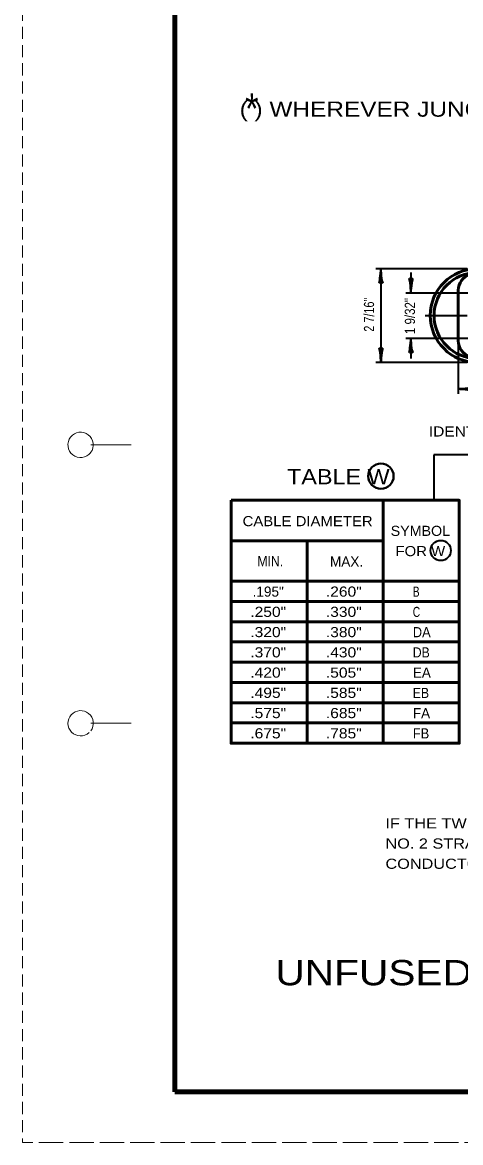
# Model space of a CAD drawing. Extents: x -1 to 679, y 0 to 440.
# Drawn here: x -1.3 to 85.1, y -0.1 to 221.2 of the extents above; entities that cross this region are included whole.
import ezdxf
from ezdxf.enums import TextEntityAlignment as Align

# ---------------------------------------------------------------- set-up
doc = ezdxf.new("R2010")
doc.units = 0
doc.header["$LTSCALE"] = 0.8
doc.linetypes.add('LONG_DASHED', pattern=[7.5, 6, -1.5])
doc.linetypes.add('MEDIUM_DASHED', pattern=[4.5, 3, -1.5])
doc.layers.add('1', color=7, linetype='Continuous', lineweight=53)
doc.layers.add('61', color=7, linetype='Continuous', lineweight=35)

msp = doc.modelspace()

# ---------------------------------------------------------------- linework, layer by layer
at = {"layer": '1', "linetype": 'MEDIUM_DASHED', "lineweight": 13}
msp.add_line((-1.285, 439.9088), (-1.345, -0.1312), dxfattribs=at)
at = {"layer": '1', "lineweight": 35}
for p, q in [((86.3878, 172.5118), (68.3878, 172.5118)), ((69.3878, 172.5118), (69.3878, 154.0118)), ((75.3062, 171.7618), (75.3062, 167.7618)), ((74.3062, 167.7618), (87.3878, 167.7618)), ((78.1378, 163.2618), (86.3878, 163.2618)), ((74.3062, 158.7618), (87.3878, 158.7618)), ((75.3062, 158.7618), (75.3062, 154.7618)), ((84.6378, 157.2618), (84.6378, 147.7618)), ((86.3878, 154.0118), (68.3878, 154.0118)), ((84.6378, 148.7618), (92.1378, 148.7618)), ((122.1378, 135.7618), (79.8449, 135.7618)), ((79.8449, 135.7618), (79.8449, 126.7763))]:
    msp.add_line(p, q, dxfattribs=at)
at = {"layer": '1'}
for p, q in [((84.6378, 167.7618), (84.6378, 163.2618)), ((84.6378, 163.2618), (84.6378, 158.7618)), ((69.8449, 78.7763), (69.8449, 126.7763)), ((39.8449, 118.7763), (69.8449, 118.7763)), ((54.8449, 78.7763), (54.8449, 118.7763)), ((39.8449, 110.7763), (84.8449, 110.7763)), ((39.8449, 106.7763), (84.8449, 106.7763)), ((39.8449, 102.7763), (84.8449, 102.7763)), ((39.8449, 98.7763), (84.8449, 98.7763)), ((39.8449, 94.7763), (84.8449, 94.7763)), ((39.8449, 90.7763), (84.8449, 90.7763)), ((39.8449, 86.7763), (84.8449, 86.7763)), ((39.8449, 82.7763), (84.8449, 82.7763))]:
    msp.add_line(p, q, dxfattribs=at)
msp.add_lwpolyline([(39.8449, 126.7763), (84.8449, 126.7763), (84.8449, 78.7763), (39.8449, 78.7763)], close=True, dxfattribs=at)
for radius in [9.25, 8.5]:
    msp.add_circle((88.3878, 163.2618), radius, dxfattribs=at)
at = {"layer": '1', "lineweight": 40}
msp.add_circle((69.4018, 131.5274), 2.5, dxfattribs=at)
at = {"layer": '1', "lineweight": 35}
msp.add_circle((81.2019, 116.8432), 2, dxfattribs=at)
at = {"layer": '1'}
for centre, start, end in [((88.3878, 168.0039), 356.30478, 183.69522), ((88.3878, 158.5196), 176.30478, 3.69522)]:
    msp.add_arc(centre, 3.7578, start, end, dxfattribs=at)
at = {"layer": '1', "lineweight": 40}
for centre, major_axis, ratio, start_param, end_param in [((69.1762, 171.3912), (0.1757, 1.7565), 0.07063, 3.14071475, 5.41810995), ((69.1762, 171.3912), (0.1757, 1.7565), 0.07063, 3.14071475, 5.41810995), ((69.6641, 171.4206), (-0.1562, 1.7857), 0.122415, 0.89635335, 3.14159265), ((69.6641, 171.4206), (-0.1562, 1.7857), 0.122415, 0.89635335, 3.14159265), ((75.03, 168.8529), (0.1562, -1.7857), 0.122415, 0.89635335, 3.14159265), ((75.5179, 168.8823), (-0.1757, -1.7565), 0.07063, 3.14071475, 5.41810995), ((75.0946, 157.6412), (0.1757, 1.7565), 0.07063, 3.14071475, 5.41810995), ((75.5825, 157.6706), (-0.1562, 1.7857), 0.122415, 0.89635335, 3.14159265), ((69.1115, 155.1029), (0.1562, -1.7857), 0.122415, 0.89635335, 3.14159265), ((69.5994, 155.1323), (-0.1757, -1.7565), 0.07063, 3.14071475, 5.41810995), ((85.7583, 148.5501), (-1.7565, 0.1757), 0.07063, 3.14071475, 5.41810995), ((85.7583, 148.5501), (-1.7565, 0.1757), 0.07063, 3.14071475, 5.41810995), ((85.729, 149.038), (-1.7857, -0.1562), 0.122415, 0.89635335, 3.14159265), ((85.729, 149.038), (-1.7857, -0.1562), 0.122415, 0.89635335, 3.14159265)]:
    msp.add_ellipse(centre, major_axis=major_axis, ratio=ratio, start_param=start_param, end_param=end_param, dxfattribs=at)
at = {"layer": '61', "lineweight": 13}
for p, q in [((12.135, 137.7288), (20.135, 137.7288)), ((12.155, 82.7088), (20.135, 82.7088))]:
    msp.add_line(p, q, dxfattribs=at)
at = {"layer": '61', "lineweight": 158}
msp.add_line((667.775, 9.8688), (28.715, 9.8888), dxfattribs=at)
at = {"layer": '61', "linetype": 'LONG_DASHED', "lineweight": 13}
msp.add_line((678.715, -0.1112), (-1.345, -0.1312), dxfattribs=at)
at = {"layer": '61', "lineweight": 158}
msp.add_lwpolyline([(667.755, 429.9088), (28.715, 429.9088), (28.715, 9.8888)], dxfattribs=at)
at = {"layer": '61', "lineweight": 13}
for centre, start, end in [((10.1328, 137.7101), 322.67175, 321.71615), ((10.1328, 82.7101), 323.13009, 312.31439)]:
    msp.add_arc(centre, 2.5, start, end, dxfattribs=at)

# ---------------------------------------------------------------- texts
at = {"layer": '1'}
for s, height, width, p in [('*', 6, 0.85, (42.5986, 201.1527)), ('( ) WHEREVER JUNCTION BOXES ARE USED FOR WIRE PULLING PURPOSES ONLY.', 3, 1.2, (41.5177, 202.5465)), ('IDENTIFYING SYMBOLS IV', 2, 1.15, (78.8437, 139.3612)), ('TABLE W', 3, 1.15, (50.8732, 129.9235)), ('CABLE DIAMETER', 2, 1.1, (42.1023, 121.6432)), ('MIN.', 2, 0.9, (45.0202, 113.7299)), ('B', 2, 0.75, (75.6902, 107.7084)), ('C', 2, 0.75, (75.6902, 103.7084)), ('DA', 2, 0.95, (75.6902, 99.7084)), ('DB', 2, 0.9, (75.6902, 95.7084)), ('EB', 2, 0.9, (75.6902, 87.7084)), ('FB', 2, 0.95, (75.6902, 79.7084)), ('IF THE TWIN CABLE OUTSIDE DIAMETER W IS .54" AND THEIR CONDUCTOR X IS', 2, 1.2, (70.2921, 61.9532)), ('NO. 2 STRANDED, AND THE SINGLE CABLE OUTSIDE DIAMETER Y IS .29" AND THE', 2, 1.2, (70.2921, 57.9532)), ('CONDUCTOR Z IS NO. 12 STRANDED, THE KIT REQUIRED WILL BE IV-EB1-C6.', 2, 1.2, (70.2921, 53.9532))]:
    msp.add_text(s, height=height, dxfattribs=dict(at, width=width)).set_placement(p)
for s, width, p in [('2 7/16"', 0.8, (68.0446, 160.076)), ('1 9/32"', 0.85, (76.1142, 159.6012))]:
    msp.add_text(s, height=2, rotation=90, dxfattribs=dict(at, width=width)).set_placement(p)
for s, height, width, p in [('SYMBOL', 2, 1.05, (77.1816, 119.7243)), ('FOR W', 2, 1.1, (77.1815, 115.7243)), ('.260"', 2, 1.15, (62.0735, 107.7252)), ('.250"', 2, 1.15, (47.1599, 103.7252)), ('.330"', 2, 1.15, (62.0735, 103.7252)), ('.320"', 2, 1.15, (47.1599, 99.7252)), ('.380"', 2, 1.15, (62.0735, 99.7252)), ('.370"', 2, 1.15, (47.1599, 95.7252)), ('.430"', 2, 1.15, (62.0735, 95.7252)), ('.420"', 2, 1.15, (47.1599, 91.7252)), ('.505"', 2, 1.15, (62.0735, 91.7252)), ('.495"', 2, 1.15, (47.1599, 87.7252)), ('.585"', 2, 1.15, (62.0735, 87.7252)), ('.575"', 2, 1.15, (47.1599, 83.7252)), ('.685"', 2, 1.15, (62.0735, 83.7252)), ('.675"', 2, 1.15, (47.1599, 79.7252)), ('.785"', 2, 1.15, (62.0735, 79.7252)), ('UNFUSED "Y" CONNECTOR KIT FOR PULL BOX', 5, 1.2, (139.244, 30.9443))]:
    msp.add_text(s, height=height, dxfattribs=dict(at, width=width)).set_placement(p, align=Align.CENTER)
for s, p in [('MAX.', (59.3502, 113.6651)), ('EA', (75.6902, 91.7084)), ('FA', (75.6902, 83.7084))]:
    msp.add_text(s, height=2, dxfattribs=at).set_placement(p)
msp.add_text('.195"', height=2, dxfattribs=at).set_placement((47.16, 107.7252), align=Align.CENTER)

doc.saveas('drawing.dxf')
